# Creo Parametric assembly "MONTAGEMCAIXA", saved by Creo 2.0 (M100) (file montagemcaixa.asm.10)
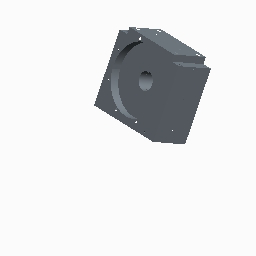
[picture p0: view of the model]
Units: millimeter Newton Second (mmNs); MM, TONNE, SECS

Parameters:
  PTC_COMMON_NAME = "montagemcaixa.asm"

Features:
  1. datum plane "ASM_RIGHT"
  2. datum plane "ASM_TOP"
  3. datum plane "ASM_FRONT"
  4. coordinate system
  5. component "SUPORTEMANCALINFERIOR"
  6. component "SUPORTEMANCALSUPERIOR"
  7. component "MANCAL1"
  8. component "ESPACADORMANCAL"
  9. component "ESPACADORMANCAL"
  10. component "TAMPALATERAL"

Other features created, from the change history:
  component "ESPACADORMANCAL.PRT"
